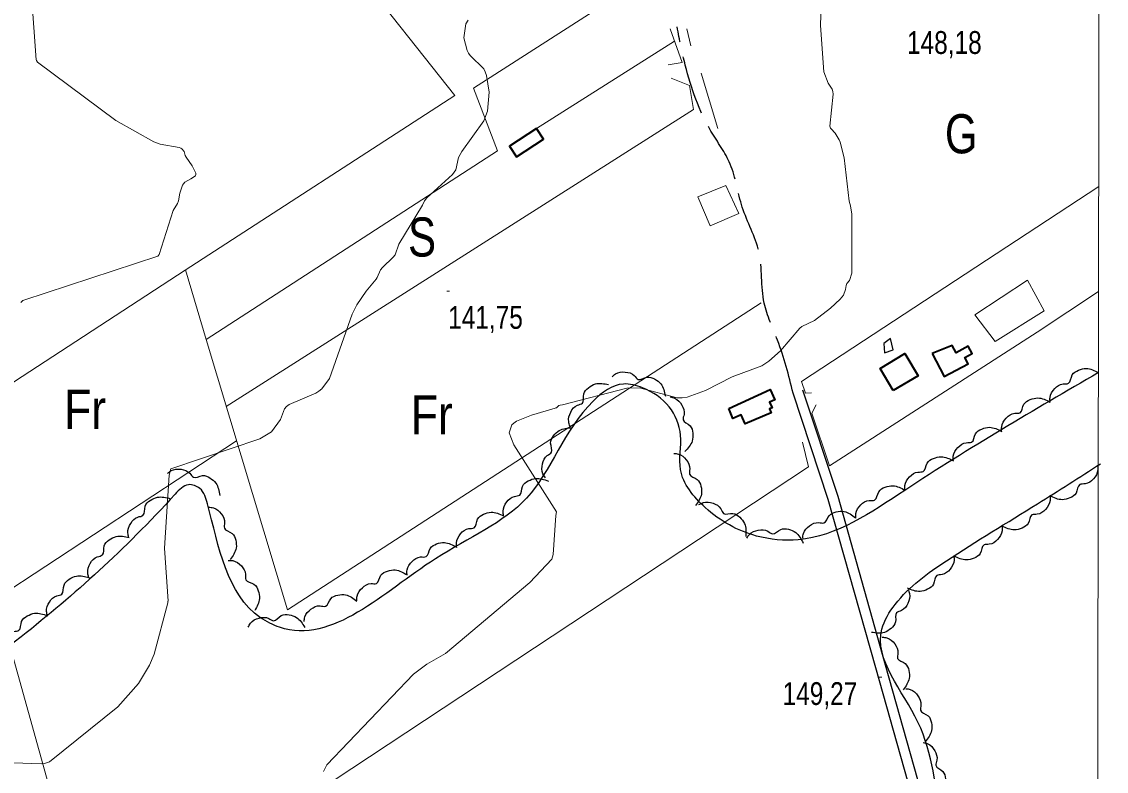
# Model space of a CAD drawing. Extents: x 483843 to 488449, y 4381269 to 4384483.
# Drawn here: x 487262.3 to 487678, y 4382174.3 to 4382461.7 of the extents above; entities that cross this region are included whole.
import ezdxf
from ezdxf.enums import TextEntityAlignment as Align

# ---------------------------------------------------------------- set-up
doc = ezdxf.new("R2010")
doc.units = 0
doc.header["$LTSCALE"] = 3.8
doc.linetypes.add('LONG_DASHED', pattern=[7.5, 6, -1.5])
for name, color, linetype, lineweight in [('1', 7, 'Continuous', 13), ('21', 7, 'Continuous', 25), ('27', 7, 'Continuous', 25), ('38', 7, 'Continuous', 25), ('47', 7, 'Continuous', 35), ('51', 7, 'Continuous', 13), ('7', 7, 'Continuous', 13), ('9', 7, 'Continuous', 13)]:
    doc.layers.add(name, color=color, linetype=linetype, lineweight=lineweight)
doc.layers.add('31', color=7, linetype='Continuous')

msp = doc.modelspace()

# ---------------------------------------------------------------- linework, layer by layer
at = {"layer": '1'}
msp.add_lwpolyline([(484100.5, 4384135.8), (487678, 4384129), (487674.1, 4381816.7), (484095.6, 4381823.6)], close=True, dxfattribs=at)
at = {"layer": '21'}
msp.add_lwpolyline([(487596.27, 4382335.89), (487595.28, 4382340.15), (487592.69, 4382338.22), (487592.99, 4382334.7)], close=True, dxfattribs=at)
at = {"layer": '27'}
for points in [[(486286.37, 4382818.73), (486339.99, 4382829.8), (486391.37, 4382851.5), (486440.09, 4382863.84), (486483.65, 4382864.6), (486530.94, 4382876.91), (486556.13, 4382891.91), (486581.09, 4382903.76), (486654.31, 4382924.49), (486662.47, 4382925.04), (486711.17, 4382931.08), (486727.4, 4382937.04), (486766.91, 4382937.87), (486808.31, 4382909.18), (486821.81, 4382880.51), (486820.67, 4382841.64), (486812.49, 4382812.89), (486799.42, 4382770.69), (486791.78, 4382745.03), (486785, 4382714.29), (486784.58, 4382691.25), (486792.33, 4382675.66), (486812.73, 4382668.89), (486834.8, 4382649.92), (486842.09, 4382627.43), (486847.24, 4382607.13), (486841.07, 4382582.93), (486840.3, 4382544.36), (486820.33, 4382480.87), (486817.63, 4382459.06), (486815.97, 4382420.47), (486812.52, 4382387.85), (486799.99, 4382362.84), (486771.04, 4382337.85), (486733.51, 4382314.2), (486712.72, 4382296.59), (486687.38, 4382263.88), (486690.96, 4382229.15), (486713.22, 4382200.82), (486764.33, 4382192.43), (486778.5, 4382149.68), (486779.01, 4382117.89), (486787.15, 4382072.98), (486813.93, 4382065.66), (486857.54, 4382071.08), (486866.35, 4382080.34), (486893.23, 4382096.95), (486915.85, 4382116.25), (486928.06, 4382127.9), (486936.43, 4382157.7), (486928.1, 4382176.05), (486914.22, 4382205.24), (486902.98, 4382218.81), (486885.61, 4382249.79), (486879.29, 4382279.36), (486884.99, 4382315.26), (486888.52, 4382343.76), (486907.35, 4382375.88), (486922.54, 4382388.35), (486945.58, 4382366.33), (486954.28, 4382323.31), (486963.51, 4382283.6), (486982.52, 4382253.24), (487009.26, 4382225.98), (487037.6, 4382230.32), (487058.96, 4382252.37), (487069.68, 4382284.84), (487065.95, 4382338.17), (487054.24, 4382363.72), (487038.01, 4382386.56), (487027.59, 4382400.37), (487012.06, 4382422.24), (486991.9, 4382450.1), (486977.88, 4382471.56), (486976.21, 4382486.9), (486980.43, 4382521.64), (487024.88, 4382562.69), (487055.81, 4382565.06), (487106.74, 4382596.8), (487155.96, 4382614.11), (487207.74, 4382666.72), (487232.21, 4382676.6), (487267.31, 4382683.94), (487282.71, 4382693.48), (487294.56, 4382707.98), (487340.16, 4382736.84), (487389.67, 4382736.07), (487421.36, 4382716.33), (487454.29, 4382680.57), (487455.44, 4382629.06), (487501.37, 4382598.97)], [(487674.99, 4382327.12), (487600.73, 4382281.96), (487559.96, 4382263.02), (487543.94, 4382264.48), (487524.28, 4382275.4), (487514.82, 4382289.97), (487514.82, 4382303.08), (487510.45, 4382314.01), (487500.26, 4382321.29), (487492.98, 4382322.75), (487481.33, 4382316.2), (487455.84, 4382279.05), (487420.9, 4382255.74), (487361.2, 4382229.51), (487353.92, 4382233.16), (487333.53, 4382276.86), (487330.62, 4382282.69), (487326.25, 4382284.15), (487321.15, 4382280.5), (487262.18, 4382225.87), (487217.04, 4382194.55), (487186.46, 4382174.88), (487179.18, 4382164.69), (487185.01, 4382145.02), (487193.01, 4382101.31), (487202.48, 4382091.85), (487210.49, 4382084.56), (487220.68, 4382080.92), (487233.79, 4382087.47), (487262.91, 4382104.96), (487326.98, 4382145.75), (487337.9, 4382147.93), (487343, 4382145.02), (487345.91, 4382133.36), (487351.73, 4382112.24), (487364.11, 4382095.49), (487370.66, 4382086.75), (487375.76, 4382079.46), (487377.94, 4382072.18), (487375.76, 4382064.89), (487372.12, 4382058.34), (487375.03, 4382046.68), (487383.77, 4382031.39), (487391.05, 4382027.75), (487408.52, 4382034.3), (487418.71, 4382042.31), (487424.54, 4382039.4), (487429.63, 4382034.3), (487461.67, 4381974.57), (487471.13, 4381957.09), (487476.96, 4381938.88), (487483.51, 4381921.4), (487488.61, 4381921.4), (487500.26, 4381922.13), (487520.64, 4381925.04), (487535.93, 4381938.88), (487546.12, 4381962.92), (487537.39, 4382014.63), (487516.27, 4382080.19), (487500.26, 4382117.34), (487508.26, 4382137.01), (487522.1, 4382155.22), (487538.84, 4382166.87), (487551.22, 4382168.33), (487587.62, 4382141.38), (487611.65, 4382126.81), (487615.29, 4382133.36), (487617.47, 4382140.65), (487615.29, 4382155.22), (487605.83, 4382193.09), (487591.99, 4382228.79), (487597.09, 4382238.26), (487616.75, 4382255.01), (487651.69, 4382276.86), (487675.72, 4382292.16)], [(487488.58, 4382325.48), (487489.95, 4382326.62), (487493.67, 4382327.34), (487497.11, 4382325.99), (487498.56, 4382324.54), (487502.02, 4382325.4), (487504.91, 4382324.68), (487507.27, 4382322.79), (487509.01, 4382318.14)], [(487656.46, 4382315.85), (487656.43, 4382317.62), (487658.21, 4382320.98), (487661.42, 4382322.8), (487663.46, 4382323.02), (487664.97, 4382326.24), (487667.35, 4382328.04), (487670.3, 4382328.69), (487675, 4382327.12)], [(487472.5, 4382306.58), (487471.98, 4382308.28), (487472.76, 4382311.99), (487475.33, 4382314.63), (487477.23, 4382315.42), (487477.78, 4382318.93), (487479.57, 4382321.32), (487482.22, 4382322.76), (487487.18, 4382322.56)], [(487510.91, 4382317.8), (487512.62, 4382317.32), (487515.33, 4382314.67), (487516.17, 4382311.07), (487515.81, 4382309.05), (487518.47, 4382306.7), (487519.53, 4382303.9), (487519.31, 4382300.89), (487516.47, 4382296.82)], [(487637.93, 4382304.58), (487637.9, 4382306.35), (487639.68, 4382309.71), (487642.89, 4382311.53), (487644.93, 4382311.75), (487646.43, 4382314.97), (487648.82, 4382316.77), (487651.77, 4382317.42), (487656.47, 4382315.85)], [(487463.04, 4382286.83), (487462.11, 4382288.34), (487461.93, 4382292.13), (487463.76, 4382295.34), (487465.4, 4382296.57), (487465.05, 4382300.11), (487466.17, 4382302.87), (487468.38, 4382304.94), (487473.23, 4382305.99)], [(487619.39, 4382293.31), (487619.37, 4382295.08), (487621.14, 4382298.44), (487624.35, 4382300.26), (487626.4, 4382300.48), (487627.9, 4382303.7), (487630.28, 4382305.5), (487633.24, 4382306.15), (487637.94, 4382304.58)], [(487512.24, 4382296.15), (487514, 4382295.91), (487517.05, 4382293.65), (487518.36, 4382290.2), (487518.28, 4382288.15), (487521.23, 4382286.17), (487522.65, 4382283.55), (487522.85, 4382280.53), (487520.58, 4382276.12)], [(487600.86, 4382282.04), (487600.84, 4382283.81), (487602.61, 4382287.17), (487605.82, 4382288.99), (487607.86, 4382289.21), (487609.37, 4382292.43), (487611.75, 4382294.23), (487614.7, 4382294.88), (487619.41, 4382293.31)], [(487318.25, 4382288.48), (487319.67, 4382289.54), (487323.43, 4382290.05), (487326.78, 4382288.51), (487328.16, 4382286.98), (487331.65, 4382287.64), (487334.5, 4382286.76), (487336.75, 4382284.74), (487338.22, 4382280)], [(487674.7, 4382291.51), (487674.76, 4382289.74), (487673.05, 4382286.35), (487669.88, 4382284.46), (487667.85, 4382284.19), (487666.41, 4382280.94), (487664.06, 4382279.09), (487661.12, 4382278.39), (487656.39, 4382279.86)], [(487447.05, 4382272.23), (487446.82, 4382273.99), (487448.21, 4382277.52), (487451.19, 4382279.69), (487453.19, 4382280.15), (487454.32, 4382283.52), (487456.49, 4382285.58), (487459.35, 4382286.56), (487464.2, 4382285.52)], [(487582.01, 4382271.32), (487582.03, 4382273.09), (487583.91, 4382276.39), (487587.17, 4382278.12), (487589.22, 4382278.28), (487590.82, 4382281.46), (487593.25, 4382283.19), (487596.22, 4382283.75), (487600.88, 4382282.03)], [(487656.42, 4382279.83), (487656.47, 4382278.05), (487654.74, 4382274.68), (487651.56, 4382272.81), (487649.52, 4382272.56), (487648.06, 4382269.32), (487645.7, 4382267.49), (487642.76, 4382266.8), (487638.03, 4382268.31)], [(487303.44, 4382263.95), (487303.05, 4382265.68), (487304.11, 4382269.33), (487306.88, 4382271.76), (487308.83, 4382272.4), (487309.65, 4382275.86), (487311.61, 4382278.11), (487314.37, 4382279.34), (487319.3, 4382278.76)], [(487521.89, 4382276.51), (487523.49, 4382277.27), (487527.28, 4382277.05), (487530.27, 4382274.89), (487531.33, 4382273.13), (487534.88, 4382273.1), (487537.51, 4382271.68), (487539.33, 4382269.26), (487539.85, 4382264.33)], [(487334.06, 4382275.55), (487335.82, 4382275.29), (487338.84, 4382273), (487340.13, 4382269.54), (487340.02, 4382267.49), (487342.96, 4382265.49), (487344.36, 4382262.85), (487344.53, 4382259.84), (487342.22, 4382255.44)], [(487429.04, 4382260.13), (487428.93, 4382261.9), (487430.55, 4382265.34), (487433.67, 4382267.31), (487435.7, 4382267.63), (487437.05, 4382270.92), (487439.34, 4382272.83), (487442.26, 4382273.61), (487447.04, 4382272.26)], [(487561.64, 4382263.67), (487561.93, 4382265.42), (487564.28, 4382268.4), (487567.76, 4382269.63), (487569.81, 4382269.49), (487571.86, 4382272.39), (487574.52, 4382273.74), (487577.55, 4382273.85), (487581.9, 4382271.47)], [(487540.2, 4382263.64), (487541.23, 4382265.08), (487544.64, 4382266.74), (487548.31, 4382266.32), (487550.09, 4382265.29), (487553.21, 4382267), (487556.19, 4382267.05), (487558.96, 4382265.83), (487561.82, 4382261.78)], [(487638.05, 4382268.3), (487638.1, 4382266.52), (487636.36, 4382263.15), (487633.17, 4382261.29), (487631.13, 4382261.05), (487629.66, 4382257.81), (487627.3, 4382255.98), (487624.36, 4382255.3), (487619.64, 4382256.82)], [(487288.1, 4382248.61), (487287.67, 4382250.33), (487288.62, 4382254), (487291.32, 4382256.52), (487293.25, 4382257.21), (487293.97, 4382260.69), (487295.87, 4382262.99), (487298.59, 4382264.31), (487303.53, 4382263.87)], [(487410.01, 4382249.69), (487410.05, 4382251.46), (487411.96, 4382254.74), (487415.24, 4382256.44), (487417.29, 4382256.58), (487418.92, 4382259.74), (487421.37, 4382261.45), (487424.34, 4382261.98), (487428.98, 4382260.22)], [(487341.51, 4382255.12), (487343.29, 4382255.04), (487346.52, 4382253.07), (487348.15, 4382249.75), (487348.25, 4382247.7), (487351.37, 4382246), (487353.02, 4382243.52), (487353.49, 4382240.53), (487351.64, 4382235.93)], [(487619.54, 4382256.98), (487619.69, 4382255.21), (487618.15, 4382251.75), (487615.07, 4382249.71), (487613.05, 4382249.34), (487611.77, 4382246.03), (487609.51, 4382244.07), (487606.61, 4382243.22), (487601.81, 4382244.47)], [(487390.78, 4382239.66), (487390.88, 4382241.43), (487392.9, 4382244.64), (487396.23, 4382246.23), (487398.29, 4382246.3), (487400.02, 4382249.41), (487402.53, 4382251.03), (487405.52, 4382251.46), (487410.1, 4382249.55)], [(487272.25, 4382233.81), (487271.88, 4382235.54), (487272.96, 4382239.18), (487275.76, 4382241.59), (487277.71, 4382242.21), (487278.56, 4382245.67), (487280.54, 4382247.9), (487283.31, 4382249.11), (487288.23, 4382248.48)], [(487602.02, 4382244.08), (487602.61, 4382242.4), (487601.98, 4382238.66), (487599.51, 4382235.92), (487597.64, 4382235.06), (487597.23, 4382231.53), (487595.54, 4382229.07), (487592.94, 4382227.52), (487587.98, 4382227.53)], [(487370.59, 4382231.72), (487370.88, 4382233.47), (487373.21, 4382236.46), (487376.7, 4382237.69), (487378.74, 4382237.55), (487380.79, 4382240.45), (487383.45, 4382241.81), (487386.48, 4382241.93), (487390.83, 4382239.55)], [(487255.27, 4382220.3), (487255.01, 4382222.05), (487256.33, 4382225.61), (487259.27, 4382227.84), (487261.27, 4382228.33), (487262.33, 4382231.72), (487264.46, 4382233.82), (487267.3, 4382234.86), (487272.17, 4382233.91)], [(487349.13, 4382229.57), (487350.04, 4382231.1), (487353.31, 4382233.02), (487357, 4382232.89), (487358.85, 4382232.01), (487361.82, 4382233.97), (487364.79, 4382234.25), (487367.65, 4382233.26), (487370.83, 4382229.45)], [(487592.14, 4382225.68), (487593.9, 4382225.41), (487596.9, 4382223.1), (487598.16, 4382219.62), (487598.04, 4382217.57), (487600.96, 4382215.55), (487602.33, 4382212.9), (487602.47, 4382209.88), (487600.13, 4382205.51)], [(487601.13, 4382205.95), (487602.87, 4382205.63), (487605.82, 4382203.23), (487606.98, 4382199.73), (487606.8, 4382197.68), (487609.67, 4382195.58), (487610.97, 4382192.89), (487611.03, 4382189.87), (487608.57, 4382185.56)], [(487607.84, 4382185.35), (487609.55, 4382184.86), (487612.24, 4382182.19), (487613.06, 4382178.59), (487612.69, 4382176.57), (487615.34, 4382174.2), (487616.38, 4382171.4), (487616.15, 4382168.39), (487613.28, 4382164.34)]]:
    msp.add_spline(points, degree=3, dxfattribs=at)
at = {"layer": '38'}
for points in [[(487674.26, 4381913.66), (487662.14, 4381954.3), (487648.71, 4382005.02), (487642.45, 4382024.62), (487631.99, 4382065.8), (487611.62, 4382135.96), (487589.66, 4382213.95), (487571.44, 4382278.52), (487557.99, 4382319.19)], [(487674.29, 4381927.56), (487665.92, 4381955.36), (487652.48, 4382006.12), (487646.22, 4382025.7), (487635.78, 4382066.83), (487615.39, 4382137.04), (487593.44, 4382215.01), (487575.19, 4382279.67), (487561.71, 4382320.42)]]:
    msp.add_lwpolyline(points, dxfattribs=at)
at = {"layer": '38', "linetype": 'LONG_DASHED'}
msp.add_spline([(487557.99, 4382319.19), (487552.01, 4382339.54), (487546.92, 4382353.76), (487544.86, 4382373.45), (487538.5, 4382390.56), (487533.88, 4382407.04), (487526.49, 4382419.71), (487516.66, 4382444.93), (487513.5, 4382459.64)], degree=3, dxfattribs=at)
at = {"layer": '47'}
for points in [[(487459.64, 4382420.72), (487449.3, 4382413.92), (487451.99, 4382409.83), (487462.33, 4382416.63)], [(487596.37, 4382320.22), (487591.28, 4382328.71), (487600.8, 4382334.41), (487605.89, 4382325.92)], [(487611.22, 4382334.41), (487615.91, 4382325.65), (487625.01, 4382330.52), (487623.72, 4382332.9), (487626.54, 4382334.43), (487625.03, 4382337.2), (487620.4, 4382334.69), (487618.9, 4382337.45)], [(487533.29, 4382313.35), (487549.18, 4382320.66), (487550.98, 4382316.72), (487548.93, 4382315.78), (487549.89, 4382313.67), (487548.96, 4382313.27), (487549.61, 4382311.74), (487539.59, 4382307.48), (487538.13, 4382310.89), (487534.89, 4382309.52)]]:
    msp.add_lwpolyline(points, close=True, dxfattribs=at)
at = {"layer": '51'}
for p, q in [((487518.75, 4382452.4), (487517.19, 4382458.97)), ((487512.52, 4382454.16), (487459.64, 4382420.72)), ((487529.17, 4382420.67), (487522.72, 4382441.91)), ((487333, 4382339.77), (487325.06, 4382366.46)), ((487252.67, 4382240.56), (487344.67, 4382301.01))]:
    msp.add_line(p, q, dxfattribs=at)
for points in [[(487537.56, 4382833.81), (487602.08, 4382714.56), (487669.71, 4382586.44), (487435.47, 4382436.11), (487444.74, 4382412.08), (487333, 4382339.77), (487364.19, 4382236.17), (487545.79, 4382353.89)], [(487350.98, 4382531.06), (487428.4, 4382433.34), (487324.94, 4382366.38), (487148.84, 4382251.47)], [(487510.13, 4382445.1), (487515.44, 4382445.96), (487510.82, 4382458.91)], [(487511.29, 4382439.95), (487518.25, 4382437.24), (487519.79, 4382427.97), (487340.71, 4382314.18)], [(487565.04, 4382319.34), (487562.71, 4382319.29), (487561.19, 4382323.76), (487675.08, 4382398.52)], [(487675.01, 4382358.22), (487651.55, 4382342.6), (487571.92, 4382291.43), (487565.2, 4382311.62), (487566.78, 4382314.8)], [(487289.45, 4382108.6), (487382.94, 4382168), (487381.76, 4382170.68), (487563.83, 4382290.96), (487561.53, 4382300.44)], [(487252.62, 4382240.93), (487289.45, 4382108.6), (487196.77, 4382050.11), (487264.44, 4381817.49)]]:
    msp.add_lwpolyline(points, dxfattribs=at)
for points in [[(487521.46, 4382394.48), (487526.2, 4382383.33), (487537.2, 4382388.14), (487532.17, 4382398.91)], [(487627.56, 4382349.22), (487635.35, 4382339.03), (487654.23, 4382350.83), (487647.84, 4382362.55)]]:
    msp.add_lwpolyline(points, close=True, dxfattribs=at)
at = {"layer": '7'}
for p, q in [((487425.27, 4382358.28), (487426.27, 4382358.28)), ((487590.97, 4382210.31), (487591.97, 4382210.31))]:
    msp.add_line(p, q, dxfattribs=at)
at = {"layer": '9'}
for points in [[(487262.79, 4382517.89), (487267.87, 4382446.97), (487268.06, 4382446.73), (487268.45, 4382446.08), (487298.43, 4382423.78), (487312.94, 4382415.56), (487315.42, 4382414.69), (487322.68, 4382413.37), (487323.28, 4382413.17), (487323.77, 4382412.95), (487324.55, 4382411.93), (487325.04, 4382410.35), (487325.34, 4382409.77), (487327.67, 4382406.34), (487329.07, 4382403.63), (487329.1, 4382403.05), (487328.97, 4382402.55), (487327.21, 4382401.35), (487324.87, 4382400.09)], [(487568.95, 4382476.06), (487568.42, 4382460.24), (487569.74, 4382442.37), (487571.44, 4382438.06), (487572.92, 4382435.79), (487573.14, 4382434.88), (487573.27, 4382433.86), (487572.01, 4382421.61), (487572.34, 4382420.89), (487572.54, 4382420.61), (487574.09, 4382418.86), (487575.61, 4382416.4), (487575.99, 4382415.44), (487577.55, 4382409.44), (487579.42, 4382392.89), (487579.95, 4382391), (487580.49, 4382387.88), (487580.45, 4382365.29), (487579.54, 4382362.45), (487578.62, 4382361.24), (487578.45, 4382360.87), (487578.31, 4382360.48), (487578.11, 4382358.96), (487577.24, 4382356.87), (487575.97, 4382355.32), (487572.28, 4382351.8), (487566.2, 4382347.1), (487561.37, 4382344.76), (487560.5, 4382344.17), (487553.14, 4382335.48), (487548.71, 4382331.49), (487545.99, 4382329.78), (487534.64, 4382325.46), (487524.36, 4382320.3), (487517.37, 4382317.68), (487515.44, 4382317.46), (487513.53, 4382317.46), (487499.08, 4382321.24), (487494.29, 4382321.21), (487469.65, 4382314.74), (487468.65, 4382314.6), (487468.24, 4382314.46), (487467.77, 4382314.1)], [(487259.23, 4382177.54), (487269.77, 4382177.19), (487271.14, 4382177.33), (487273, 4382177.95), (487299.22, 4382199.05), (487307.05, 4382207.95), (487311.28, 4382214.95), (487313.15, 4382219.15), (487318.31, 4382238.85), (487318.4, 4382239.44), (487318.42, 4382239.46), (487318.43, 4382239.47), (487318.47, 4382239.49), (487317.06, 4382259.86), (487318.82, 4382287.82), (487319.52, 4382290.17), (487353.61, 4382301.7), (487358.12, 4382304.4), (487361.55, 4382309.16), (487363.06, 4382313.23), (487363.86, 4382314.14), (487364.84, 4382314.95), (487375.07, 4382319.2), (487376.27, 4382320), (487377.36, 4382320.9), (487380.34, 4382324.92), (487388.98, 4382349.56), (487390.74, 4382353.15), (487394.38, 4382358.36), (487398.15, 4382362.9), (487398.63, 4382363.6), (487399.87, 4382366.56), (487400.58, 4382367.44), (487404.71, 4382371.33), (487405.44, 4382372.32), (487406.84, 4382376.33), (487415.93, 4382391.36), (487416.66, 4382392.94), (487417.61, 4382394.13), (487427.41, 4382403.11), (487428.7, 4382404.82), (487429.75, 4382409.64), (487431.05, 4382411.83), (487439.47, 4382423.61), (487440.81, 4382427.41), (487441.44, 4382434.67), (487440.41, 4382441.02), (487439.95, 4382442.37), (487439.41, 4382443.54), (487434.19, 4382448.66), (487433.61, 4382449.59), (487433.11, 4382450.66), (487431.84, 4382455.51), (487432.61, 4382460.83), (487433.39, 4382462.2)], [(487324.87, 4382400.09), (487324.37, 4382399.54), (487323.95, 4382398.92), (487322.97, 4382395.94), (487322.39, 4382393.02), (487322.04, 4382391.93), (487320.39, 4382389.22), (487315.09, 4382372.36), (487314.69, 4382371.91), (487314.47, 4382371.73), (487263.17, 4382354.85), (487262.84, 4382354.71), (487262.56, 4382354.56), (487262.04, 4382353.95)], [(487467.77, 4382314.1), (487467.47, 4382313.76), (487467.39, 4382313.7), (487467.31, 4382313.65), (487467.03, 4382313.56), (487466.79, 4382313.55), (487466.82, 4382313.53), (487457.73, 4382310.84), (487452.01, 4382308.51), (487450.97, 4382307.79), (487450.16, 4382307.04), (487449.18, 4382304.03), (487450.98, 4382299.46), (487467.34, 4382273.8), (487467.09, 4382272.29), (487466.07, 4382257.45), (487465.55, 4382255.56), (487457.07, 4382246.71), (487424.8, 4382219.44), (487417.67, 4382215.35), (487412.48, 4382211.52), (487379.28, 4382176.7), (487377.97, 4382174.23)]]:
    msp.add_lwpolyline(points, dxfattribs=at)

# ---------------------------------------------------------------- texts
at = {"layer": '31'}
for s, width, p in [('G', 0.8, (487622.41, 4382411.19)), ('S', 0.8, (487415.78, 4382371.61)), ('Fr', 0.85, (487286.66, 4382305.55)), ('Fr', 0.85, (487419.51, 4382303.47))]:
    msp.add_text(s, height=15, dxfattribs=dict(at, width=width)).set_placement(p, align=Align.CENTER)
at = {"layer": '7', "width": 0.8}
for s, p in [('148,18', (487601.62, 4382449.29)), ('141,75', (487425.77, 4382343.91)), ('149,27', (487553.94, 4382199.7))]:
    msp.add_text(s, height=8.75, dxfattribs=at).set_placement(p)

doc.saveas('drawing.dxf')
